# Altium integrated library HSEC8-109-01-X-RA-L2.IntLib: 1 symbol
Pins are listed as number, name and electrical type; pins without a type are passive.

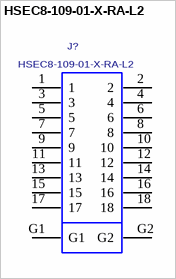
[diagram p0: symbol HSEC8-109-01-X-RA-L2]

## HSEC8-109-01-X-RA-L2
designator J?
0.8MM HIGH SPEED ASSEMBLY,18 PINS.; MANUFACTURER: SAMTEC
footprint HSEC8-109-01-X-RA-L2
pins: 1, 2, 3, 4, 5, 6, 7, 8, 9, 10, 11, 12, 13, 14, 15, 16, 17, 18, G1, G2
